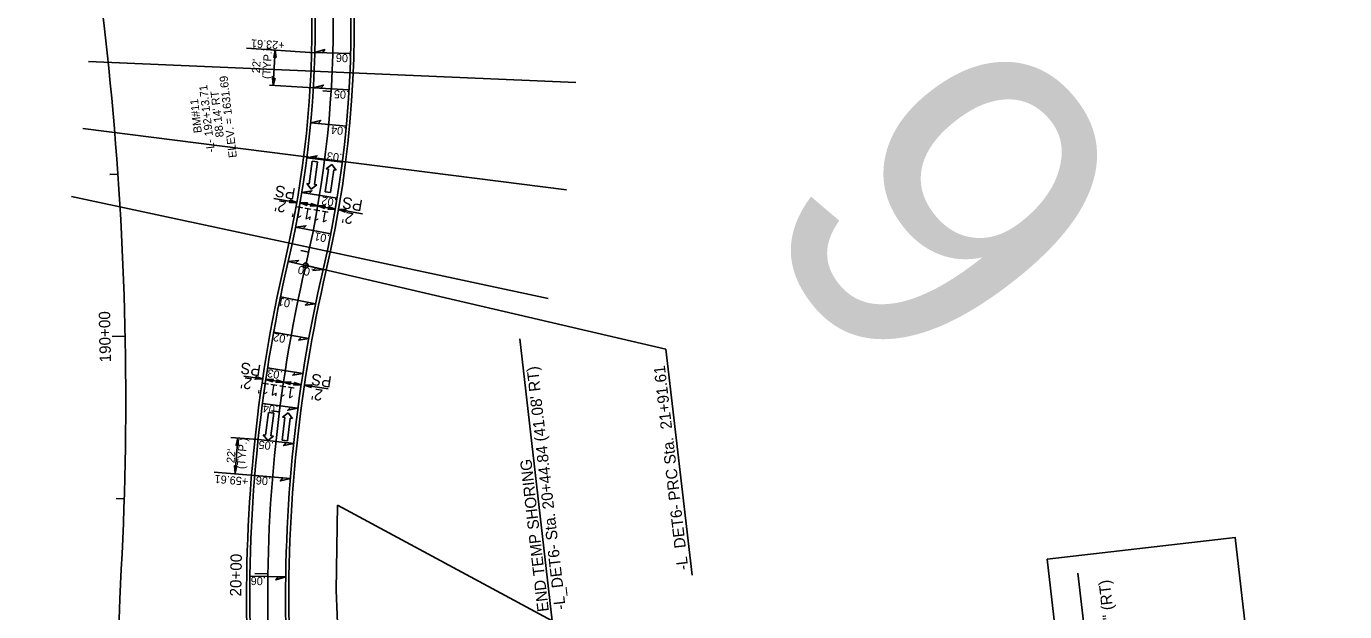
# Model space of a CAD drawing. Extents: x 473658 to 481584, y 489119 to 506230.
# Drawn here: x 474465 to 475276, y 504324 to 504684 of the extents above; entities that cross this region are included whole.
import ezdxf

# ---------------------------------------------------------------- set-up
doc = ezdxf.new("R2010")
doc.units = 0
for name, color, linetype in [('Default', 7, 'Continuous'), ('Exist Structure Minor Pipes CMP 60 Inch', 7, 'Continuous'), ('Prop Dimension', 7, 'Continuous'), ('Prop EOT', 7, 'Continuous'), ('Prop Grid Mask', 7, 'Continuous'), ('Prop Horizontal Alignment', 7, 'Continuous'), ('Prop Horizontal Alignment Curve and Spiral Data', 7, 'Continuous'), ('Prop Horizontal Alignment Station Label', 7, 'Continuous'), ('Prop Horizontal Alignment Tick Label', 7, 'Continuous'), ('Prop Horizontal Alignment Tick Large', 7, 'Continuous'), ('Prop Horizontal Alignment Tick Small', 7, 'Continuous'), ('Prop Paved Shoulder', 7, 'Continuous'), ('Prop Shade Medium', 7, 'Continuous'), ('Prop Superelevation  Arrow CELL', 7, 'Continuous'), ('Prop Superelevation Label', 7, 'Continuous'), ('Scratch_Level_6', 7, 'Continuous'), ('Sheet Block Title CELL', 7, 'Continuous')]:
    doc.layers.add(name, color=color, linetype=linetype)

msp = doc.modelspace()

# ---------------------------------------------------------------- linework, layer by layer
at = {"layer": 'Exist Structure Minor Pipes CMP 60 Inch'}
msp.add_lwpolyline([(474725.53, 503984.81), (474657.37, 504291.29), (474655.39, 504336.72), (474656.22, 504389)], dxfattribs=at)
at = {"layer": 'Prop Dimension'}
for p, q in [((474631.26, 504575.5), (474617, 504577.97)), ((474654.92, 504571.42), (474633.23, 504575.16)), ((474671.54, 504568.55), (474656.9, 504571.08)), ((474610.17, 504466.8), (474598.53, 504468.53)), ((474633.91, 504463.28), (474612.15, 504466.51)), ((474650.59, 504460.81), (474635.89, 504462.99))]:
    msp.add_line(p, q, dxfattribs=at)
for points in [[(474626.96, 504577.03), (474631.26, 504575.5), (474626.66, 504575.49), (474627.37, 504576.18)], [(474637.53, 504573.63), (474633.23, 504575.16), (474637.83, 504575.18), (474637.12, 504574.49)], [(474639.77, 504574.82), (474644.08, 504573.29), (474639.48, 504573.27), (474640.18, 504573.96)], [(474648.38, 504571.76), (474644.08, 504573.29), (474648.67, 504573.31), (474647.97, 504572.62)], [(474650.62, 504572.95), (474654.92, 504571.42), (474650.33, 504571.4), (474651.03, 504572.09)], [(474661.2, 504569.55), (474656.9, 504571.08), (474661.49, 504571.1), (474660.79, 504570.41)], [(474605.83, 504468.23), (474610.17, 504466.8), (474605.58, 504466.67), (474606.26, 504467.38)], [(474616.49, 504465.08), (474612.15, 504466.51), (474616.74, 504466.64), (474616.06, 504465.93)], [(474618.69, 504466.32), (474623.03, 504464.89), (474618.44, 504464.77), (474619.12, 504465.47)], [(474627.37, 504463.47), (474623.03, 504464.89), (474627.62, 504465.02), (474626.94, 504464.32)], [(474629.58, 504464.71), (474633.91, 504463.28), (474629.32, 504463.15), (474630.01, 504463.86)], [(474640.23, 504461.56), (474635.89, 504462.99), (474640.49, 504463.12), (474639.8, 504462.41)]]:
    msp.add_lwpolyline(points, close=True, dxfattribs=at)
at = {"layer": 'Prop EOT'}
for centre, radius, start, end in [((474003.55, 504683.86), 639, 346.91582, 43.31339), ((474003.55, 504683.86), 661, 346.91582, 22.7364), ((475513.31, 504332.97), 911, 166.91582, 182.02426), ((475513.31, 504332.97), 889, 166.91582, 182.02426)]:
    msp.add_arc(centre, radius, start, end, dxfattribs=at)
at = {"layer": 'Prop Grid Mask'}
msp.add_lwpolyline([(475160.21, 503770.12), (475092.92, 504355.81), (475208.66, 504369.11), (475275.95, 503783.42)], close=True, dxfattribs=at)
at = {"layer": 'Prop Horizontal Alignment'}
for centre, radius, start, end in [((474003.55, 504683.86), 650, 346.91582, 43.31339), ((472540.97, 504454.71), 1985, 356.96875, 14.25965), ((475513.31, 504332.97), 900, 166.91582, 182.02426), ((475966.17, 504273.33), 1445, 176.96875, 223.37358)]:
    msp.add_arc(centre, radius, start, end, dxfattribs=at)
at = {"layer": 'Prop Horizontal Alignment Curve and Spiral Data'}
msp.add_line((475137.17, 504126.47), (475111.81, 504347.27), dxfattribs=at)
at = {"layer": 'Prop Horizontal Alignment Station Label'}
for p, q in [((474638.14, 504536.37), (474858.35, 504485.19)), ((474788.26, 504317.97), (474768.41, 504491.44)), ((474858.35, 504485.19), (474874.39, 504346.08)), ((474788.26, 504317.97), (474656.22, 504389))]:
    msp.add_line(p, q, dxfattribs=at)
msp.add_circle((474636.68, 504536.71), 1.5, dxfattribs=at)
at = {"layer": 'Prop Horizontal Alignment Tick Large'}
for p, q in [((474525.6, 504493.07), (474517.6, 504492.91)), ((474613.42, 504346.88), (474605.42, 504347))]:
    msp.add_line(p, q, dxfattribs=at)
at = {"layer": 'Prop Horizontal Alignment Tick Small'}
for p, q in [((474652.32, 504643.84), (474647.33, 504644.15)), ((474521.15, 504592.96), (474516.16, 504592.61)), ((474638.52, 504544.89), (474633.64, 504545.96)), ((474620.51, 504446.58), (474615.55, 504447.21)), ((474525.01, 504393.08), (474520.01, 504393.23))]:
    msp.add_line(p, q, dxfattribs=at)
at = {"layer": 'Prop Paved Shoulder'}
for centre, radius, start, end in [((474003.55, 504683.86), 637, 346.91582, 43.31339), ((474003.55, 504683.86), 663, 346.91582, 23.25181), ((475513.31, 504332.97), 913, 166.91582, 182.02426), ((475513.31, 504332.97), 887, 166.91582, 182.02426)]:
    msp.add_arc(centre, radius, start, end, dxfattribs=at)
at = {"layer": 'Prop Shade Medium'}
for p, q in [((474638.8, 504587), (474640.74, 504600.86)), ((474640.74, 504600.86), (474644.01, 504600.4)), ((474644.01, 504600.4), (474642.07, 504586.54)), ((474648.73, 504582.07), (474650.67, 504595.93)), ((474649.18, 504596.14), (474652.69, 504598.83)), ((474650.67, 504595.93), (474649.18, 504596.14)), ((474653.94, 504595.48), (474652, 504581.61)), ((474652.69, 504598.83), (474655.42, 504595.27)), ((474655.42, 504595.27), (474653.94, 504595.48)), ((474640.05, 504583.64), (474637.31, 504587.2)), ((474637.31, 504587.2), (474638.8, 504587)), ((474643.55, 504586.33), (474640.05, 504583.64)), ((474642.07, 504586.54), (474643.55, 504586.33)), ((474652, 504581.61), (474648.73, 504582.07)), ((474612.03, 504432.25), (474613.71, 504446.15)), ((474613.71, 504446.15), (474616.98, 504445.76)), ((474616.98, 504445.76), (474615.31, 504431.86)), ((474622.16, 504429.15), (474623.85, 504443.05)), ((474622.36, 504443.23), (474625.82, 504445.98)), ((474623.85, 504443.05), (474622.36, 504443.23)), ((474627.12, 504442.65), (474625.44, 504428.75)), ((474625.82, 504445.98), (474628.61, 504442.47)), ((474628.61, 504442.47), (474627.12, 504442.65)), ((474613.34, 504428.92), (474610.54, 504432.43)), ((474610.54, 504432.43), (474612.03, 504432.25)), ((474616.8, 504431.68), (474613.34, 504428.92)), ((474615.31, 504431.86), (474616.8, 504431.68)), ((474625.44, 504428.75), (474622.16, 504429.15))]:
    msp.add_line(p, q, dxfattribs=at)
at = {"layer": 'Prop Superelevation  Arrow CELL'}
for points in [[(474618.6, 504664.78), (474617.97, 504669.3), (474617.02, 504664.8), (474617.84, 504665.35)], [(474642.35, 504667.7), (474648.39, 504669.55), (474646.97, 504667.58)], [(474617.84, 504652.03), (474616.69, 504647.61), (474616.28, 504652.19), (474617.02, 504651.55)], [(474641.43, 504646.09), (474647.54, 504647.74), (474646.05, 504645.82)], [(474639.79, 504624.53), (474645.95, 504625.96), (474644.4, 504624.1)], [(474637.42, 504603.03), (474643.62, 504604.26), (474642.01, 504602.45)], [(474634.32, 504581.63), (474640.56, 504582.64), (474638.89, 504580.89)], [(474630.5, 504560.34), (474636.77, 504561.15), (474635.04, 504559.45)], [(474625.96, 504539.2), (474632.26, 504539.79), (474630.47, 504538.15)], [(474647.39, 504534.22), (474641.09, 504533.63), (474642.88, 504535.27)], [(474642.73, 504512.99), (474636.45, 504512.25), (474638.2, 504513.93)], [(474638.59, 504491.66), (474632.33, 504490.76), (474634.04, 504492.49)], [(474634.97, 504470.23), (474628.73, 504469.18), (474630.4, 504470.95)], [(474631.88, 504448.72), (474625.67, 504447.52), (474627.29, 504449.33)], [(474595.39, 504425.92), (474594.98, 504430.47), (474593.82, 504426.02), (474594.66, 504426.53)], [(474629.31, 504427.15), (474623.13, 504425.79), (474624.71, 504427.64)], [(474594.38, 504413.22), (474593.25, 504408.8), (474592.81, 504413.37), (474593.56, 504412.74)], [(474627.27, 504405.51), (474621.13, 504404.01), (474622.67, 504405.89)], [(474624.39, 504345.02), (474618.37, 504343.1), (474619.77, 504345.08)]]:
    msp.add_lwpolyline(points, close=True, dxfattribs=at)
at = {"layer": 'Prop Superelevation Label'}
for p, q in [((474600.21, 504670.49), (474642.35, 504667.67)), ((474616.69, 504647.61), (474617.97, 504669.3)), ((474642.35, 504667.7), (474664.34, 504667.15)), ((474614.32, 504647.7), (474641.43, 504646.09)), ((474641.43, 504646.09), (474663.39, 504644.79)), ((474639.79, 504624.53), (474661.7, 504622.49)), ((474637.42, 504603.03), (474659.24, 504600.25)), ((474634.32, 504581.63), (474656.04, 504578.11)), ((474630.5, 504560.34), (474652.08, 504556.09)), ((474625.96, 504539.2), (474647.39, 504534.22)), ((474621.18, 504517.45), (474642.73, 504512.99)), ((474616.94, 504495.59), (474638.59, 504491.66)), ((474613.24, 504473.63), (474634.97, 504470.23)), ((474610.07, 504451.59), (474631.88, 504448.72)), ((474590.57, 504430.82), (474607.44, 504429.48)), ((474593.25, 504408.8), (474594.98, 504430.48)), ((474607.44, 504429.48), (474629.31, 504427.15)), ((474580.43, 504409.35), (474605.35, 504407.31)), ((474605.35, 504407.31), (474627.27, 504405.51)), ((474602.39, 504345.32), (474624.39, 504345.02))]:
    msp.add_line(p, q, dxfattribs=at)
at = {"layer": 'Scratch_Level_6'}
for p, q in [((474503.08, 504662.29), (474802.81, 504649.35)), ((474642.35, 504667.7), (474664.34, 504667.15)), ((474641.43, 504646.09), (474663.39, 504644.79)), ((474499.57, 504620.91), (474797.19, 504583.15)), ((474639.79, 504624.53), (474661.7, 504622.49)), ((474637.42, 504603.03), (474659.24, 504600.25)), ((474492.48, 504579.22), (474785.83, 504516.43)), ((474634.32, 504581.63), (474656.04, 504578.11)), ((474630.5, 504560.34), (474652.08, 504556.09)), ((474625.96, 504539.2), (474647.39, 504534.22)), ((474621.18, 504517.45), (474642.73, 504512.99)), ((474616.94, 504495.59), (474638.59, 504491.66)), ((474613.24, 504473.63), (474634.97, 504470.23)), ((474610.07, 504451.59), (474631.88, 504448.72)), ((474607.44, 504429.48), (474629.31, 504427.15)), ((474605.35, 504407.31), (474627.27, 504405.51)), ((474602.39, 504345.32), (474624.39, 504345.02))]:
    msp.add_line(p, q, dxfattribs=at)

# ---------------------------------------------------------------- texts
at = {"layer": 'Default'}
for s, p in [('ELEV. = 1631.69', (474594.35, 504603.26)), ('-L- 192+13.71', (474580.78, 504606.54)), ("88.14' RT", (474586.31, 504615.83)), ('BM#11', (474572.8, 504618.48))]:
    msp.add_text(s, height=5, rotation=96.57729, dxfattribs=at).set_placement(p)
at = {"layer": 'Prop Dimension'}
for s, rotation, p in [('PS', 170.20607, (474630.81, 504584)), ("2'", 170.20607, (474625.17, 504575.97)), ("11'", 170.20607, (474640.84, 504571.51)), ("11'", 170.20607, (474651.42, 504569.71)), ('PS', 170.20607, (474672.14, 504576.84)), ("2'", 170.20607, (474666.5, 504568.81)), ('PS', 171.57089, (474609.52, 504475.28)), ("2'", 171.57089, (474604.07, 504467.12)), ('PS', 171.57089, (474653.04, 504468.31)), ("11'", 171.57089, (474619.85, 504463.12)), ("11'", 171.57089, (474630.46, 504461.49)), ("2'", 171.57089, (474647.59, 504460.15))]:
    msp.add_text(s, height=7, rotation=rotation, dxfattribs=at).set_placement(p)
at = {"layer": 'Prop Horizontal Alignment Curve and Spiral Data'}
msp.add_text('= 43%%d 51\' 04.3" (RT)', height=7, rotation=96.55384, dxfattribs=at).set_placement((475140.8, 504261.49))
at = {"layer": 'Prop Horizontal Alignment Station Label'}
for s, p in [("-L_DET6- Sta. 20+44.84 (41.08' RT)", (474796.75, 504325.05)), ('-L_DET6- PRC Sta.  21+91.61', (474872.17, 504349.51)), ('END TEMP SHORING', (474786.32, 504323.85))]:
    msp.add_text(s, height=7, rotation=96.57729, dxfattribs=at).set_placement(p)
at = {"layer": 'Prop Horizontal Alignment Tick Label'}
for s, rotation, p in [('190+00', 91.10709, (474516.91, 504477.08)), ('20+00', 89.11426, (474597.04, 504332.84))]:
    msp.add_text(s, height=7, rotation=rotation, dxfattribs=at).set_placement(p)
at = {"layer": 'Prop Superelevation Label'}
for s, rotation, p in [('+23.61', 176.4355, (474623.82, 504674.59)), ('(TYP.)', 86.61179, (474614.86, 504651.37)), ("22'", 86.61179, (474608.5, 504654.92)), ('.06', 178.55103, (474664.61, 504666.72)), ('.05', 176.61179, (474663.46, 504644.13)), ('.04', 174.67255, (474661.8, 504621.79)), ('.03', 172.73331, (474659.31, 504605.36)), ('.02', 170.79407, (474656.05, 504577.6)), ('.01', 168.85482, (474651.68, 504555.4)), ('.00', 166.91599, (474641.61, 504534.54)), ('.01', 168.31655, (474629.32, 504515.14)), ('.02', 169.71711, (474626.4, 504493.49)), ('.03', 171.11768, (474622.71, 504471.46)), ('.04', 172.51824, (474619.85, 504450.22)), ('(TYP.)', 85.44669, (474599.16, 504411.17)), ('.05', 173.9188, (474617.23, 504427.87)), ("22'", 85.44669, (474592.87, 504414.85)), ('+59.61', 175.31937, (474601.44, 504406.08)), ('.06', 175.31937, (474615.48, 504406.18)), ('.06', 179.22312, (474612.17, 504344.8))]:
    msp.add_text(s, height=5, rotation=rotation, dxfattribs=at).set_placement(p)
at = {"layer": 'Sheet Block Title CELL'}
msp.add_text('6', height=200, rotation=128.44881, dxfattribs=at).set_placement((475156.66, 504576.68))

doc.saveas('drawing.dxf')
